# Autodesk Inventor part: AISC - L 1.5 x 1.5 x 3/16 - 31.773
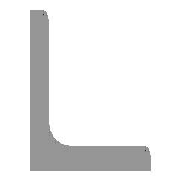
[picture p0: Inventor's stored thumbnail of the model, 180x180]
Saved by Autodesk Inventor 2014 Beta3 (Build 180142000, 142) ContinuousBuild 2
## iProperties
_CCFamilyMember: 5
_CCFamilyDisplayName: ANSI L (Equal angles) - Angle Steel
_FrameMemberDoc: Frame Member File
_Version: 15.0.0
_GetPNFromCC: 1
Created: 2010-11
Part Number: AISC - L 1.5 x 1.5 x 3/16 - 31.773
Material: Steel, Mild
Description: Angle Steel
Document SubType Name: Modeling
Standard: ANSI
Designer: Beta-8540w
Standards Organization: ANSI
Language: en-US
Size Designation: L 1.5 x 1.5 x 3/16
Categories: <MemberInstance><Categories><Category DisplayName="Structural Shapes" InternalName="089c4875-fa83-4c05-b084-43b9cc11f5ed" Mnemonic="GRDR"><CategoryParameter Dis
Stock Number: L 1.5 x 1.5 x 3/16
Density: 7.86 g/cm^3
Appearance: Steel
IsCustomPart: 1
G_L: 31.773 in
G_W: 1.500 in
G_H: 1.500 in
+EC3E699C-0520-4E89-B4DB-B1DFE966D730+CUTDETAIL1: Cut
Author: Beta-8540w
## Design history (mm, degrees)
node "Start plane"
node "End plane"
sketch "Sketch"
  geometry: L1 (38.1, 0)-(0, 0); L2 (0, 0)-(0, 38.1); L3 (0, 38.1)-(2.476, 38.1); L4 (4.762, 35.814)-(4.762, 9.589); L5 (9.588, 4.763)-(35.814, 4.763); L6 (38.1, 2.477)-(38.1, 0); L7 (0, -11.041)-(0, 31.538); L8 (-11.041, 0)-(31.538, 0); L9 (0, 48.496)-(0, -20.964) reference; L10 (-20.964, 0)-(48.496, 0) reference; A1 r 4.826 centre (9.588, 9.589) between (4.762, 9.589) and (9.588, 4.763); A2 r 2.286 centre (2.476, 35.814) between (4.762, 35.814) and (2.476, 38.1); A3 r 2.286 centre (35.814, 2.477) between (38.1, 2.477) and (35.814, 4.763); 3 further points
  constraints: 16 end point, 6 point on circle, 6 point on line, 6 tangent, 4 parallel, 3 centre point, 2 collinear, 1 equal radius, 1 horizontal, 1 perpendicular
  dimensions: "d0" = 38.1 distance between parallel lines of L6 L2 (= G_H); "d1" = 38.1 distance between parallel lines of L3 L1 (= G_H); "d2" = 4.7625 distance between parallel lines of L2 L4 (= G_T); "d3" = 4.7625 distance between parallel lines of L1 L5 (= G_T); "d10" = 0 distance between parallel lines of L7 L2 (computed from ex); "d11" = 0 distance between parallel lines of L8 L1 (computed from d10); "d14" = 4.826 radius of A1 (= G_IR); "d15" = 2.286 radius of A2 (= G_ER)
extrude "Body" new body sketch "Sketch" stored distance "d4" = 807.0404 (= G_L); taper "d5" = 0 deg
node "Driven Length"
  sketch "Sketch3"
    geometry: L1 (0, 0)-(10, 0) reference
    constraints: 2 end point, 1 horizontal
  workplane "Work Plane3"
  sketch "Sketch4"
    geometry: L1 (-2, 0)-(12, 0) reference; L2 (-2, 807.04)-(12, 807.04) reference
    dimensions: "d17" = 807.0404 distance between parallel lines of L1 L2 (derived)
workplane "Work Plane4"
split "Split1"
body "Solid1"
other parameters: "G_H" = 38.1 [user parameter; used in 2 equation terms], "G_T" = 4.7625 [user parameter; used in 2 equation terms], "G_ER" = 2.286 [user parameter; used in 1 equation term], "G_IR" = 4.826 [user parameter; used in 1 equation term], "G_L" = 807.0404 (= d17) [user parameter; used in 1 equation term], "ex" = 0 [user parameter; used in 1 equation term], "G_OFFSET_START" = 0 [user parameter; used in 1 equation term], "G_OFFSET_END" = -29.72503 [user parameter; used in 1 equation term], "d12" = 0 (computed from G_OFFSET_START), "d13" = 807.0404 (= G_OFFSET_END + B_L), "B_L" = 836.76542 [user parameter; used in 1 equation term], "d16" = 90 deg, "MAS" = 0.26787 [user parameter]
